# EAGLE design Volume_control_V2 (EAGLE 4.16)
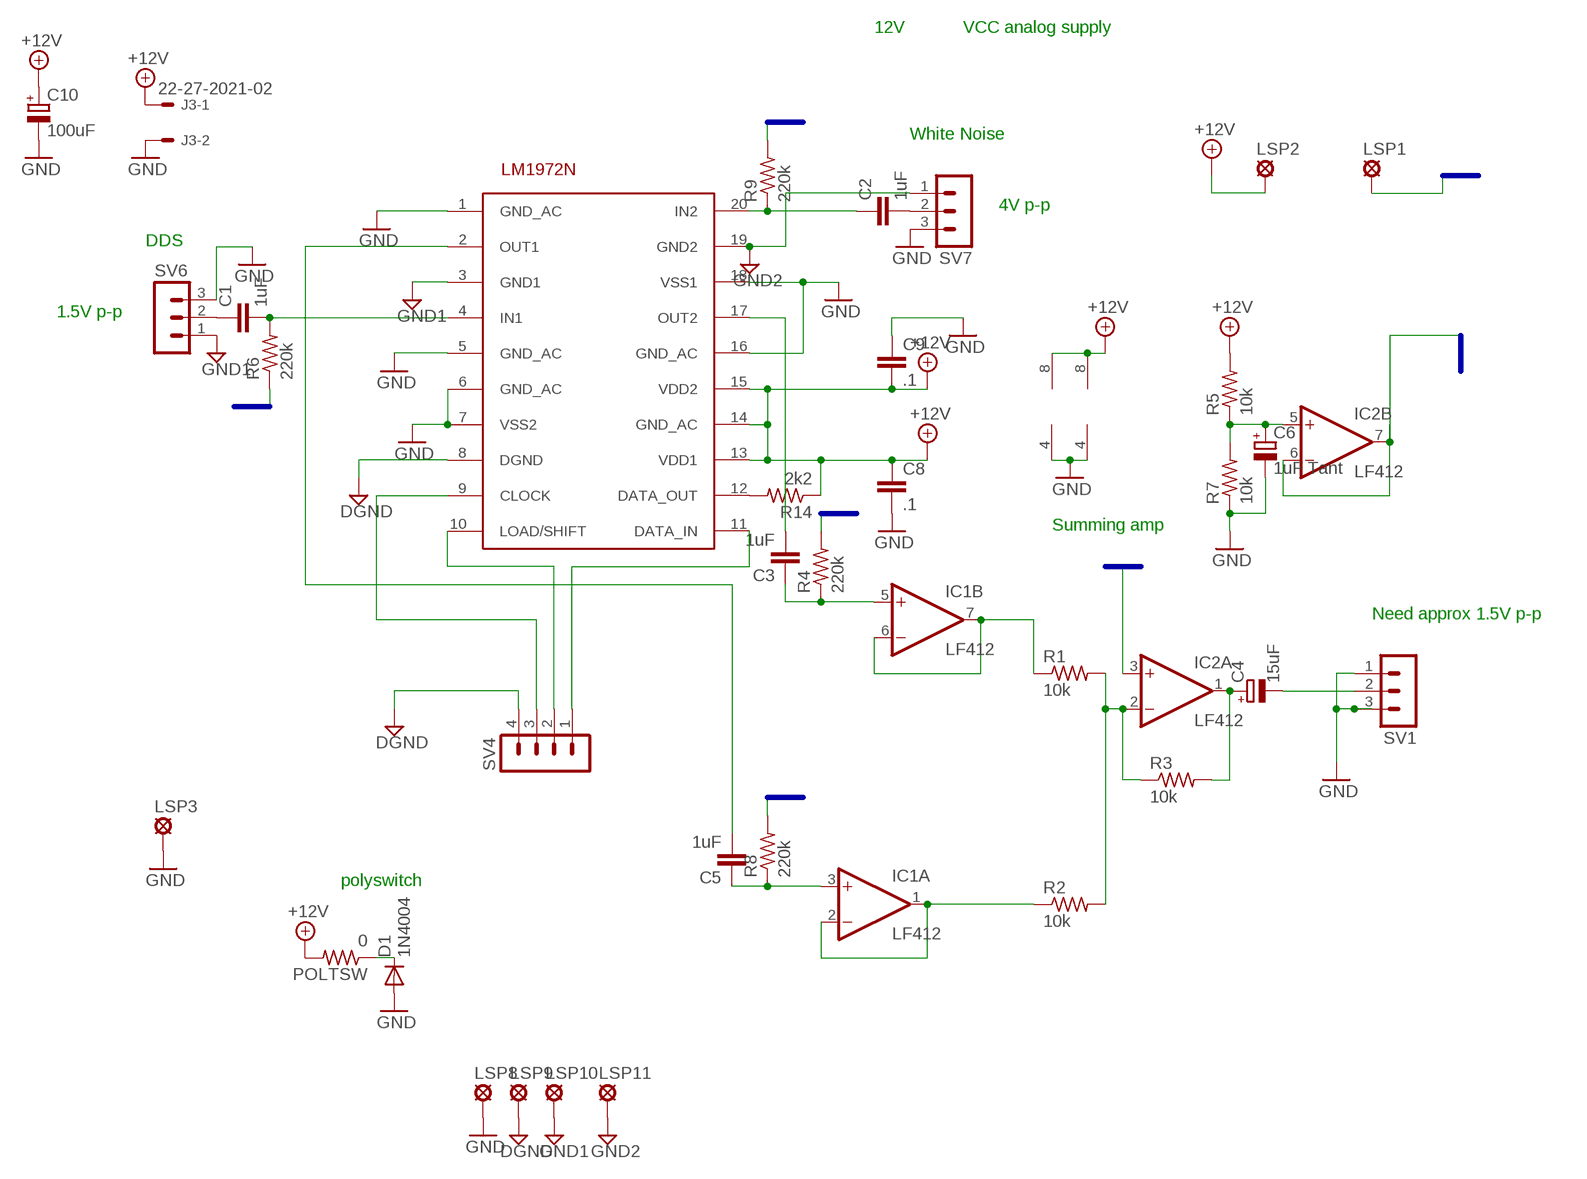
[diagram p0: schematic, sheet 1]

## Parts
C1  1uF  C-EU025-025X050  [C025-025X050]
C2  1uF  C-EU025-025X050  [C025-025X050]
C3  1uF  C-EU025-025X050  [C025-025X050]
C4  15uF  CPOL-EUE2-5  [E2-5]
C5  1uF  C-EU025-025X050  [C025-025X050]
C6  1uF Tant  CPOL-EUE2.5-4V  [E2,5RE]
C8  .1  C-EU025-025X050  [C025-025X050]
C9  .1  C-EUC0805  [C0805]
C10  100uF  CPOL-EUE2-5  [E2-5]
D1  1N4004  [DO41-10]
IC1  LF412  2AMP_P8+4N  [DIL08]
IC2  LF412  2AMP_P8+4N  [DIL08]
J3  22-27-2021-02  [6410-02]
LSP1  LSP10  [LSP10]
LSP2  LSP10  [LSP10]
LSP3  LSP10  [LSP10]
LSP8  LSP10  [LSP10]
LSP9  LSP10  [LSP10]
LSP10  LSP10  [LSP10]
LSP11  LSP10  [LSP10]
POLTSW  0  R-US_0204/2V  [0204V]
R1  10k  R-US_0204/7  [0204/7]
R2  10k  R-US_0204/7  [0204/7]
R3  10k  R-US_0204/7  [0204/7]
R4  220k  R-US_0204/7  [0204/7]
R5  10k  R-US_0204/7  [0204/7]
R6  220k  R-US_M0805  [M0805]
R7  10k  R-US_0204/7  [0204/7]
R8  220k  R-US_0204/7  [0204/7]
R9  220k  R-US_M0805  [M0805]
R14  2k2  R-US_0204/2V  [0204V]
SV1  MA03-1  [MA03-1]
SV4  MA04-1  [MA04-1]
SV6  MA03-1  [MA03-1]
SV7  MA03-1  [MA03-1]
U$1  LM1972N  [DIL-20]

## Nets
+12V [power]: C8.1 C9.2 C10.+ IC1.8(P:V+) IC2.8(P:V+) J3.1 LSP2.MP POLTSW.2 R5.2 R14.1 U$1.13(VDD1) U$1.14(GND_AC) U$1.15(VDD2)
CLOCK: SV4.3 U$1.9(CLOCK)
DATA_IN: SV4.1 U$1.11(DATA_IN)
DGND [power]: LSP9.MP SV4.4 U$1.8(DGND)
GND [power]: C6.- C8.2 C9.1 C10.- D1.A IC1.4(P:V-) IC2.4(P:V-) J3.2 LSP3.MP LSP8.MP R7.1 SV1.1 SV1.3 SV6.3 SV7.3 U$1.1(GND_AC) U$1.5(GND_AC) U$1.6(GND_AC) U$1.7(VSS2) U$1.16(GND_AC) U$1.18(VSS1)
GND1: LSP10.MP SV6.1 U$1.3(GND1)
GND2 [audio]: LSP11.MP SV7.1 U$1.19(GND2)
IN1 [audio]: C1.2 R6.2 U$1.4(IN1)
IN2 [audio]: C2.1 R9.1 U$1.20(IN2)
LOAD/SHIFT: SV4.2 U$1.10(LOAD/SHIFT)
N$3 [audio]: C4.+ IC2.1(A:OUT) R3.2
N$8 [power]: D1.C POLTSW.1
N$9: C1.1 SV6.2
N$10: R14.2 U$1.12(DATA_OUT)
N$11: C2.2 SV7.2
N$15: C6.+ IC2.5(B:+IN) R5.1 R7.2
OUT1 [audio]: C5.2 U$1.2(OUT1)
OUT1_A [audio]: C5.1 IC1.3(A:+IN) R8.1
OUT1_DIFF [audio]: IC1.6(B:-IN) IC1.7(B:OUT) R1.1
OUT2 [audio]: C3.2 U$1.17(OUT2)
OUT2_A [audio]: C3.1 IC1.5(B:+IN) R4.1
OUT2_DIFF [audio]: IC1.1(A:OUT) IC1.2(A:-IN) R2.1
OUT_DIFF [audio]: IC2.2(A:-IN) R1.2 R2.2 R3.1
TO_POWER_AMP [audio]: C4.- SV1.2
VCC/2 [power]: IC2.3(A:+IN) IC2.6(B:-IN) IC2.7(B:OUT) LSP1.MP R4.2 R6.1 R8.2 R9.2

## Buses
VCC/2

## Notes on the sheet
- 12V | VCC analog supply
- White Noise
- 4V p-p
- DDS
- 1.5V p-p
- Summing amp
- Need approx 1.5V p-p
- polyswitch

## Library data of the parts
C1-C3 C5 C8 C9 = rcl:C-EU: CAPACITOR, European symbol
C4 C6 C10 = rcl:CPOL-EU: POLARIZED CAPACITOR, European symbol
D1 = diode:1N4004: DIODE
IC1 IC2 = linear:2AMP_P8+4: OP AMP
J3 = con-molex:22-?-02: CONNECTOR
LSP1-LSP3 LSP8-LSP11 = solpad:LSP10: SOLDER PAD
POLTSW R1-R9 R14 = rcl:R-US_: RESISTOR, American symbol
SV1 SV6 SV7 = con-lstb:MA03-1: PIN HEADER
SV4 = con-lstb:MA04-1: PIN HEADER
U$1 = gs_lib:LM1972N

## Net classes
0 default: width 0.457 mm, drill 0.305 mm, clearance 0.711 mm
1 power: width 0.61 mm, drill 0.305 mm, clearance 0.711 mm
2 audio: width 0.457 mm, drill 0.305 mm, clearance 0.711 mm

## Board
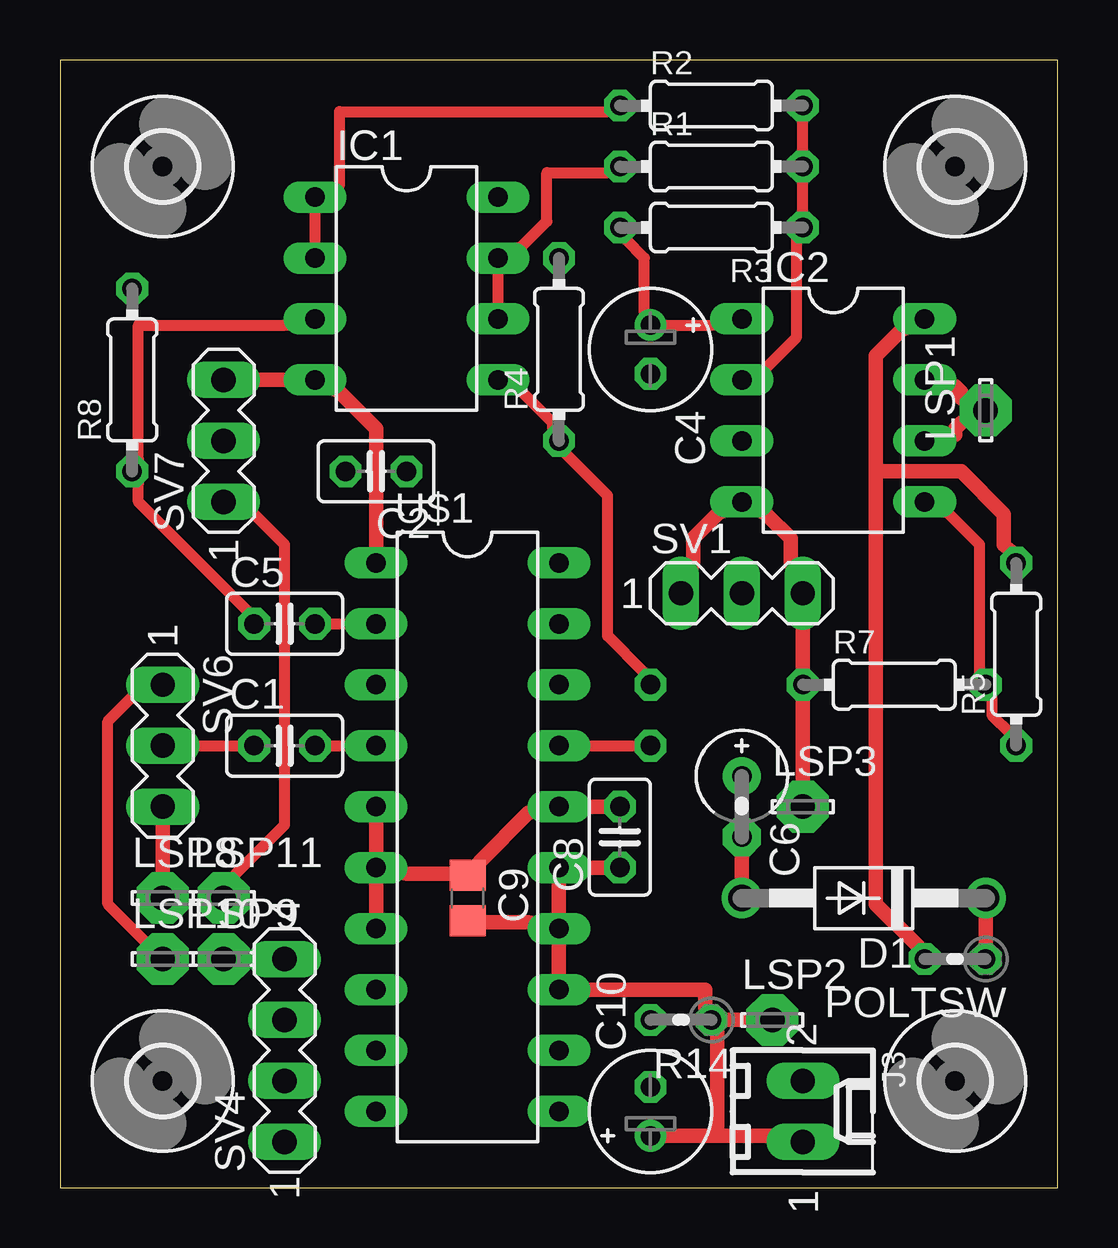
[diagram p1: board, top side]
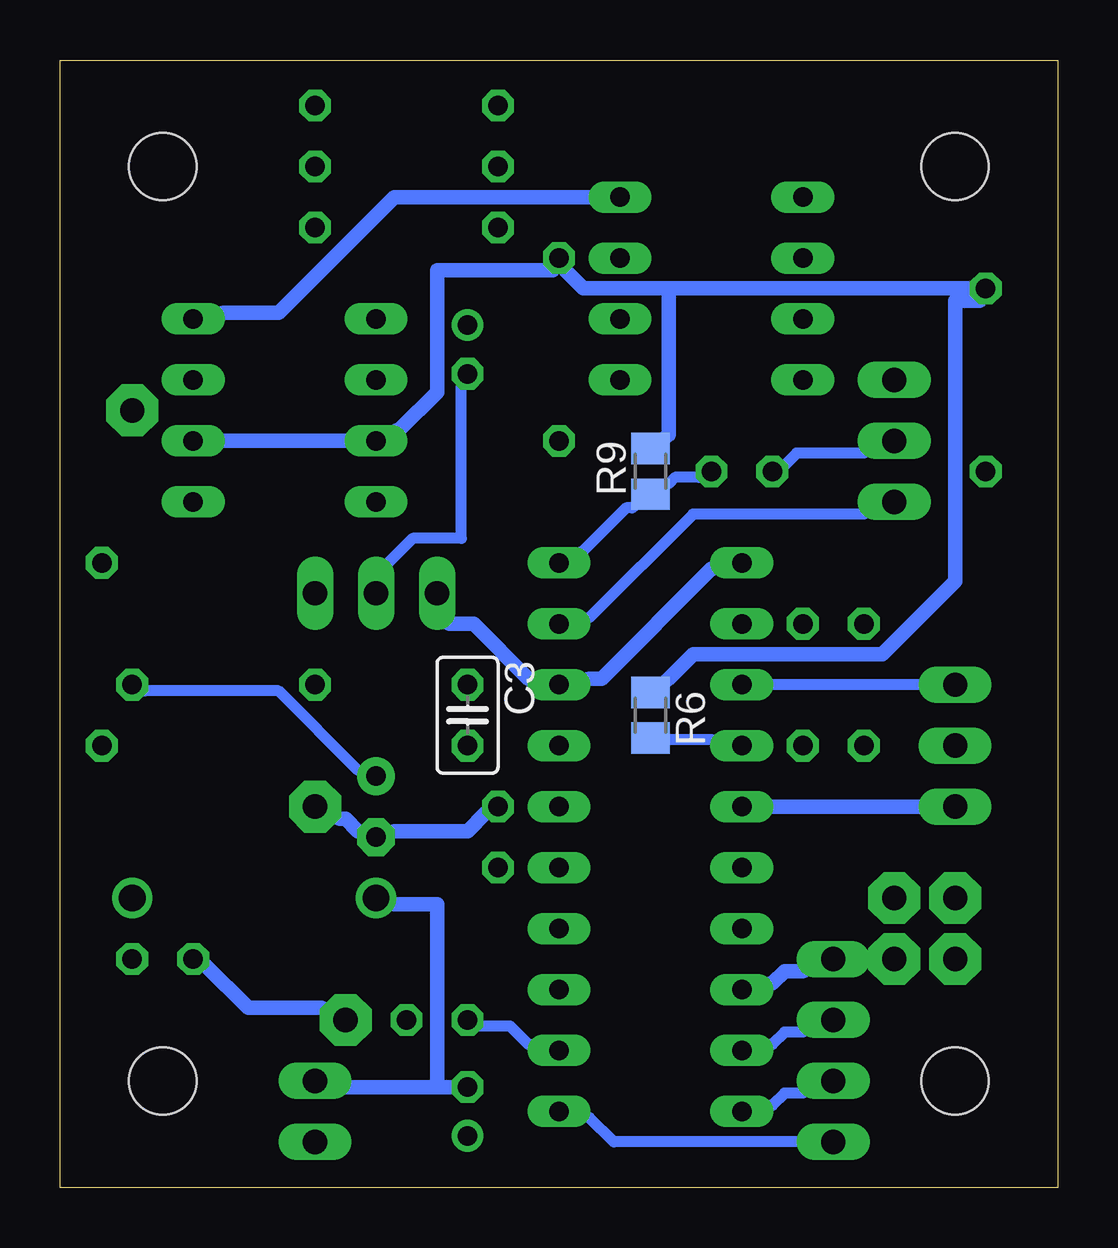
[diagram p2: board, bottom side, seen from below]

Size 41.58 x 46.98 mm. Coordinates in mm from the lower left corner, seen from the top.
Outline: 0,0 41.58,0 41.58,46.98 0,46.98 0,0
Copper layers (1*16): Top 0.035mm / dielectric 1.5mm / Bottom 0.035mm
Design rules "futurlec": minimum track width 10mil, minimum drill 28mil, track to track 10mil, track to pad 10mil, pad to pad 10mil, via to via 10mil, smd to smd 0mil, copper to edge 40mil, drill to drill 10mil, minimum pad ring 10mil, minimum via ring 8mil, stop-mask expansion 4mil, vias tented up to drill 0mil, thermal gap 10mil

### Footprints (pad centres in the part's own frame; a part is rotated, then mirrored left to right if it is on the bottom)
C025-025X050 = drill 0.813 octagon: 1 -1.27,0; 2 1.27,0
E2-5 = drill 0.813 pad 1.27 round: + -1.016,0 | drill 0.813 pad 1.27 octagon: - 1.016,0
E2,5RE = drill 0.813 pad 1.575 round: + -1.27,0 | drill 0.813 pad 1.575 octagon: - 1.27,0
C0805 = smd 1.3 x 1.5: 1 -0.95,0; 2 0.95,0
DO41-10 = drill 1.118 round: A 5.08,0; C -5.08,0
DIL08 = drill 0.813 long: 1 -3.81,-3.81; 2 -1.27,-3.81; 3 1.27,-3.81; 4 3.81,-3.81; 5 3.81,3.81; 6 1.27,3.81; 7 -1.27,3.81; 8 -3.81,3.81
6410-02 = drill 1.016 long: 1 1.27,0; 2 -1.27,0
LSP10 = drill 1.016 pad 2.159 octagon: MP 0,0
0204V = drill 0.813 octagon: 1 -1.27,0; 2 1.27,0
0204/7 = drill 0.813 octagon: 1 -3.81,0; 2 3.81,0
M0805 = smd 1.3 x 1.6: 1 -0.95,0; 2 0.95,0
MA03-1 = drill 1.016 long: 1 -2.54,0; 2 0,0; 3 2.54,0
MA04-1 = drill 1.016 long: 1 -3.81,0; 2 -1.27,0; 3 1.27,0; 4 3.81,0
DIL-20 = drill 0.813 long: 1 -11.43,-3.81; 2 -8.89,-3.81; 3 -6.35,-3.81; 4 -3.81,-3.81; 5 -1.27,-3.81; 6 1.27,-3.81; 7 3.81,-3.81; 8 6.35,-3.81; 9 8.89,-3.81; 10 11.43,-3.81; 11 11.43,3.81; 12 8.89,3.81; 13 6.35,3.81; 14 3.81,3.81; 15 1.27,3.81; 16 -1.27,3.81; 17 -3.81,3.81; 18 -6.35,3.81; 19 -8.89,3.81; 20 -11.43,3.81
2,8 = hole 2.8: 0,0

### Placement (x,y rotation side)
C1  9.36,18.41 0 top
C2  13.17,29.84 180 top
C3  24.6,19.68 270 bottom
C4  24.6,34.92 270 top
C5  9.36,23.49 0 top
C6  28.41,15.87 270 top
C8  23.33,14.6 90 top
C9  16.98,12.06 270 top
C10  24.6,3.17 90 top
D1  33.49,12.06 180 top
IC1  14.44,37.46 270 top
IC2  32.22,32.38 270 top
J3  30.95,3.17 270 top
LSP1  38.57,32.38 90 top
LSP2  29.68,6.98 0 top
LSP3  30.95,15.87 0 top
LSP8  4.28,12.06 0 top
LSP9  6.82,9.52 0 top
LSP10  4.28,9.52 0 top
LSP11  6.82,12.06 0 top
POLTSW  37.3,9.52 180 top
R1  27.14,42.54 0 top
R2  27.14,45.08 0 top
R3  27.14,40 180 top
R4  20.79,34.92 90 top
R5  39.84,22.22 90 top
R6  16.98,19.68 270 bottom
R7  34.76,20.95 0 top
R8  3.01,33.65 90 top
R9  16.98,29.84 90 bottom
R14  25.87,6.98 180 top
SV1  28.41,24.76 0 top
SV4  9.36,5.71 90 top
SV6  4.28,18.41 270 top
SV7  6.82,31.11 90 top
U$1  16.98,14.6 270 top
U$3  [2,8]  37.3,42.54 0 top
U$4  [2,8]  37.3,4.44 0 top
U$5  [2,8]  4.28,4.44 0 top
U$6  [2,8]  4.28,42.54 0 top

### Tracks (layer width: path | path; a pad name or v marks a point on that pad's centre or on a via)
+12V
  Top 0.61: C8.1 U$1.15 U$1.14 | C9.2 17.49,11.04 19.52,11.04 U$1.14 | U$1.14 U$1.13 26.89,8.25 26.89,7.49 R14.1 | 27.39,2.15 29.68,2.15 J3.1 | C10.+ 27.39,2.15 | R14.1 LSP2.MP | 27.39,2.15 27.39,6.47 R14.1 | 34,29.84 37.55,29.84 39.33,28.06 39.33,26.79 39.59,26.54 R5.2 | 34,29.84 34,34.67 35.01,35.68 IC2.8 | POLTSW.2 35.78,10.03 34,11.81 34,29.84
  Bottom 0.61: POLTSW.2 35.52,9.27 33.74,7.49 30.7,7.49 LSP2.MP | IC1.8 27.65,41.27 32.47,36.44 34.76,36.44 IC2.8
CLOCK
  Bottom 0.457: U$1.9 11.9,5.96 11.39,6.47 10.63,6.47 SV4.3
DATA_IN
  Bottom 0.457: U$1.11 19.52,2.92 18.5,1.9 SV4.1
DGND
  Top 0.61: LSP9.MP SV4.4
  Bottom 0.61: U$1.8 11.9,8.5 11.39,9.01 10.63,9.01 SV4.4
GND
  Top 0.61: LSP8.MP SV6.3 | C8.2 U$1.16 19.52,15.62 17.49,13.58 C9.1 16.47,13.08 14.44,13.08 U$1.6 | U$1.6 U$1.7 | U$1.5 U$1.6 | C6.- D1.A | SV7.3 IC1.4 11.65,33.14 13.17,31.62 U$1.1 | SV1.1 26.38,26.03 26.38,27.05 27.39,28.06 IC2.4 29.43,28.06 30.44,27.05 30.44,26.03 SV1.3 R7.1 LSP3.MP
  Bottom 0.61: SV6.3 U$1.5 | 25.87,4.19 29.68,4.19 J3.2 | 25.87,4.19 C10.- | LSP3.MP 29.93,15.36 29.68,15.36 29.17,14.85 C6.- 27.65,14.85 24.6,14.85 23.84,15.62 C8.2 | 25.87,4.19 25.87,11.81 27.65,11.81 D1.A | SV1.1 25.36,23.49 24.35,23.49 22.06,21.2 U$1.18 19.52,21.2 19.01,21.2 14.44,25.78 U$1.1
GND1
  Top 0.457: LSP10.MP 1.99,11.81 1.99,19.43 3.01,20.44 SV6.1
  Bottom 0.457: SV6.1 U$1.3
GND2
  Top 0.457: LSP11.MP 7.33,13.08 9.36,15.11 9.36,26.79 8.09,28.06 SV7.1
  Bottom 0.457: U$1.19 19.52,23.74 15.2,28.06 8.09,28.06 SV7.1
IN1
  Top 0.457: C1.2 U$1.4
  Bottom 0.457: R6.2 16.22,18.66 14.44,18.66 U$1.4
IN2
  Bottom 0.457: C2.1 14.95,29.59 15.96,29.59 16.22,29.33 R9.1 17.74,28.32 18,28.32 19.77,26.54 U$1.20
LOAD/SHIFT
  Bottom 0.457: U$1.10 11.9,3.42 11.39,3.93 10.63,3.93 SV4.2
N$3
  Top 0.457: IC2.1 27.14,35.94 C4.+ 24.35,36.44 24.35,38.73 23.58,39.49 R3.2
N$8
  Top 0.61: POLTSW.1 D1.C
N$9
  Top 0.457: SV6.2 C1.1
N$10
  Bottom 0.457: U$1.12 22.06,5.96 22.82,6.73 24.09,6.73 R14.2
N$11
  Bottom 0.457: C2.2 11.39,30.09 10.88,30.6 8.09,30.6 SV7.2
N$15
  Top 0.457: R5.1 39.59,18.92 38.82,19.68 38.82,20.44 R7.2 38.32,21.46 38.32,26.79 37.05,28.06 IC2.5
  Bottom 0.457: C6.+ 29.17,17.39 32.47,20.7 38.06,20.7 R7.2
OUT1
  Top 0.457: C5.2 U$1.2
OUT1_A
  Top 0.457: C5.1 7.84,24 3.26,28.57 3.26,29.33 R8.1 3.26,30.35 3.26,35.94 9.36,35.94 IC1.3
OUT1_DIFF
  Top 0.457: IC1.6 IC1.7 19.27,39.24 20.28,40.25 20.28,42.29 22.82,42.29 R1.1
OUT2
  Top 0.457: U$1.17 C3.2
OUT2_A
  Top 0.457: C3.1 24.35,21.46 22.82,22.98 22.82,28.82 21.04,30.6 R4.1 20.54,31.62 20.54,31.87 19.27,33.14 IC1.5
OUT2_DIFF
  Top 0.457: IC1.2 IC1.1 11.65,41.78 11.65,44.83 22.82,44.83 R2.1
OUT_DIFF
  Top 0.457: R2.2 R1.2 R3.1 30.7,39.49 30.7,35.43 29.43,34.16 IC2.2
TO_POWER_AMP
  Bottom 0.457: C4.- 24.85,33.4 24.85,27.05 26.89,27.05 27.9,26.03 SV1.2
VCC/2
  Top 0.61: IC2.7 37.3,33.4 37.55,33.14 37.55,32.89 LSP1.MP 37.55,31.87 37.3,31.62 37.3,31.36 IC2.6
  Bottom 0.61: IC2.6 IC2.3 27.39,31.62 25.87,33.14 25.87,38.22 21.04,38.22 R4.2 20.54,38.22 19.77,37.46 16.22,37.46 | R6.1 16.22,21.2 15.2,22.22 7.33,22.22 4.28,25.27 4.28,36.95 3.26,36.95 R8.2 16.22,37.46 | 16.22,37.46 16.22,31.36 R9.2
